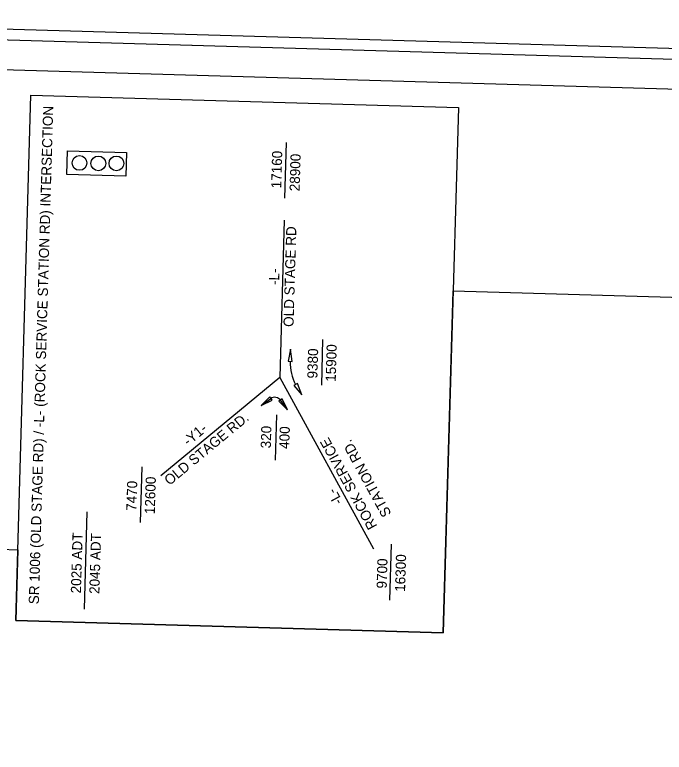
# Model space of a CAD drawing. Extents: x 2097000 to 2098148, y 684979 to 687012.
# Drawn here: x 2097260.6 to 2097531.6, y 686534.2 to 686842.1 of the extents above; entities that cross this region are included whole.
import ezdxf

# ---------------------------------------------------------------- set-up
doc = ezdxf.new("R2010")
doc.units = 0
for name, color, linetype in [('Prop PHM Legend CELL', 7, 'Continuous'), ('Prop PHM Text', 7, 'Continuous'), ('Prop PHM Traffic Signal CELL', 7, 'Continuous'), ('Sheet Layout Plan Border', 7, 'Continuous'), ('Sheet Plot Border Inside CELL', 7, 'Continuous'), ('Sheet Plot Border Outside CELL', 7, 'Continuous'), ('Sheet Profile CELL', 7, 'Continuous')]:
    doc.layers.add(name, color=color, linetype=linetype)

msp = doc.modelspace()

# ---------------------------------------------------------------- linework, layer by layer
at = {"layer": 'Prop PHM Legend CELL'}
msp.add_lwpolyline([(2097260.99, 686589.19), (2097267.36, 686808.47), (2097445.71, 686803.29), (2097439.33, 686584)], close=True, dxfattribs=at)
at = {"layer": 'Prop PHM Text'}
for p, q in [((2097373.31, 686765.44), (2097373.99, 686788.7)), ((2097373.06, 686756.37), (2097371.15, 686690.68)), ((2097388.64, 686687.48), (2097389.19, 686706.47)), ((2097371.14, 686690.68), (2097321.52, 686649.55)), ((2097371.15, 686690.68), (2097410.33, 686619.13)), ((2097363.38, 686678.97), (2097367.29, 686681.77)), ((2097374.39, 686677.14), (2097371.59, 686681.05)), ((2097369.8, 686675.07), (2097369.25, 686656.07)), ((2097313.12, 686630.11), (2097313.79, 686653.36)), ((2097289.64, 686593.89), (2097290.8, 686634.58)), ((2097417.11, 686597.72), (2097417.77, 686620.97))]:
    msp.add_line(p, q, dxfattribs=at)
for points in [[(2097375.66, 686702.41), (2097374.68, 686697.38), (2097376.36, 686697.33)], [(2097380.4, 686683.32), (2097378.5, 686688.08), (2097377.06, 686687.21)], [(2097363.38, 686678.97), (2097367.98, 686681.22), (2097367, 686682.59)], [(2097374.39, 686677.14), (2097372.14, 686681.74), (2097370.77, 686680.76)]]:
    msp.add_lwpolyline(points, close=True, dxfattribs=at)
for centre, radius, start, end in [((2097394.23, 686696.57), 18.72, 177.5863, 208.4782), ((2097369.08, 686679.26), 3.08, 35.5589, 125.5553)]:
    msp.add_arc(centre, radius, start, end, dxfattribs=at)
at = {"layer": 'Prop PHM Traffic Signal CELL'}
for p, q in [((2097282.36, 686775.4), (2097282.65, 686785.31)), ((2097282.65, 686785.31), (2097307.18, 686784.6)), ((2097307.18, 686784.6), (2097306.89, 686774.69)), ((2097306.89, 686774.69), (2097282.36, 686775.4))]:
    msp.add_line(p, q, dxfattribs=at)
for centre in [(2097287.61, 686780.22), (2097295.46, 686779.99), (2097303.02, 686779.99)]:
    msp.add_circle(centre, 3.08, dxfattribs=at)
at = {"layer": 'Sheet Layout Plan Border'}
msp.add_lwpolyline([(2098090.85, 685704.42), (2097236.93, 685318.96), (2097029.37, 685324.99), (2097067.15, 686624.39), (2097254.37, 686618.95), (2097261.85, 686618.73), (2097260.99, 686589.19), (2097439.33, 686584), (2097443.49, 686726.82), (2098120, 686707.16)], close=True, dxfattribs=at)
at = {"layer": 'Sheet Plot Border Inside CELL'}
msp.add_lwpolyline([(2098077, 685140.47), (2098125.43, 686806.26), (2097070.77, 686836.92), (2097022.35, 685171.13)], close=True, dxfattribs=at)
at = {"layer": 'Sheet Plot Border Outside CELL'}
msp.add_lwpolyline([(2098099.07, 685126.82), (2098148, 686810.11), (2097048.47, 686842.07), (2096999.53, 685158.79)], close=True, dxfattribs=at)
at = {"layer": 'Sheet Profile CELL'}
msp.add_lwpolyline([(2097072.96, 686824.36), (2097029.37, 685324.99), (2098078.93, 685294.48), (2098122.52, 686793.84)], close=True, dxfattribs=at)

# ---------------------------------------------------------------- texts
at = {"layer": 'Prop PHM Text'}
for s, height, rotation, p in [('SR 1006 (OLD STAGE RD) / -L- (ROCK SERVICE STATION RD) INTERSECTION', 4.2188, 88.3348, (2097270.63, 686595.9)), ('17160', 4.219, 88.3079, (2097371.75, 686769.54)), ('28900', 4.219, 88.3079, (2097379.43, 686768.31)), ('OLD STAGE RD ', 4.2188, 88.3617, (2097376.9, 686711.7)), ('-L- ', 4.219, 88.3617, (2097370.85, 686729.18)), ('15900', 4.219, 88.3617, (2097394.5, 686688.76)), ('9380', 4.219, 88.3617, (2097386.83, 686690.15)), ('OLD STAGE RD.', 4.2187, 39.6512, (2097325.15, 686645.35)), ('320', 4.219, 88.3348, (2097367.41, 686660.98)), ('400', 4.219, 88.3348, (2097375.11, 686660.76)), ('-Y1-', 4.219, 39.6512, (2097332.97, 686661.84)), ('ROCK SERVICE ', 4.2188, 118.707, (2097411.92, 686628.56)), ('STATION RD.', 4.2188, 118.707, (2097417.85, 686633.77)), ('12600', 4.219, 88.3079, (2097319.01, 686633.49)), ('7470', 4.219, 88.3079, (2097311.34, 686634.88)), ('-L-', 4.219, 118.707, (2097397.55, 686638.76)), ('2025 ADT', 4.219, 88.3348, (2097288.19, 686600.43)), ('2045 ADT', 4.219, 88.3348, (2097295.89, 686600.2)), ('9700', 4.219, 88.3348, (2097415.76, 686602.47)), ('16300', 4.219, 88.3348, (2097423.43, 686601.08))]:
    msp.add_text(s, height=height, rotation=rotation, dxfattribs=at).set_placement(p)

doc.saveas('drawing.dxf')
